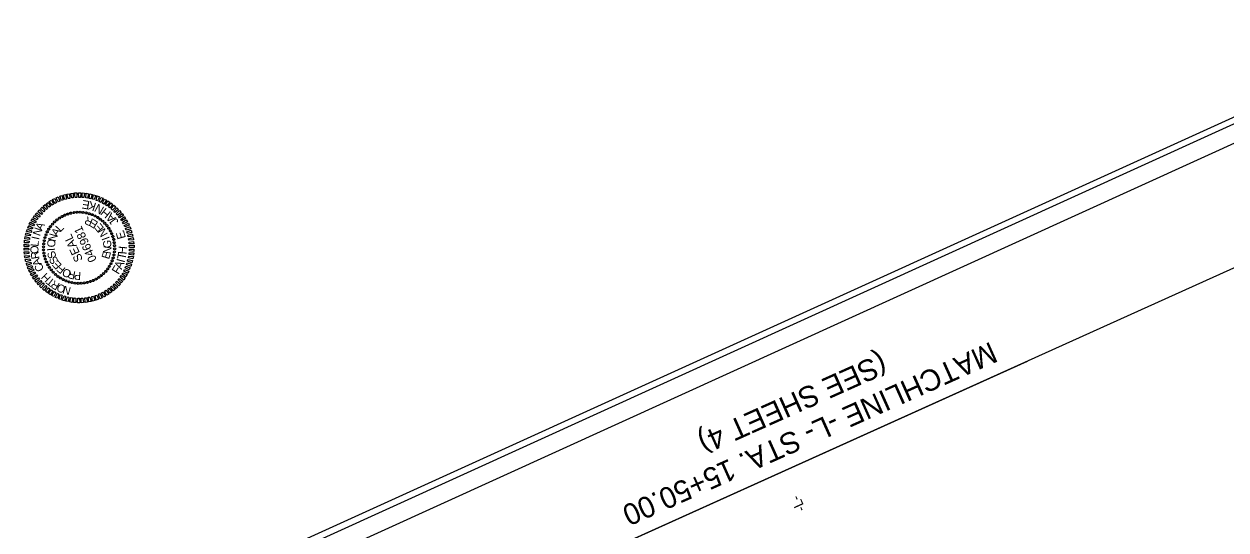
# Model space of a CAD drawing. Extents: x 2097307 to 2099001, y 683921 to 685907.
# Drawn here: x 2097307 to 2098154, y 685550 to 685907 of the extents above; entities that cross this region are included whole.
import ezdxf

# ---------------------------------------------------------------- set-up
doc = ezdxf.new("R2010")
doc.units = 0
for name, color, linetype in [('Matchline', 7, 'Continuous'), ('Matchline Text', 7, 'Continuous'), ('Prop Horizontal Alignment Station Label', 7, 'Continuous'), ('Sheet Layout Plan Border', 7, 'Continuous'), ('Sheet PE Seal Cell', 7, 'Continuous'), ('Sheet Plan CELL', 7, 'Continuous'), ('Sheet Plot Border Inside CELL', 7, 'Continuous'), ('Sheet Plot Border Outside CELL', 7, 'Continuous')]:
    doc.layers.add(name, color=color, linetype=linetype)

msp = doc.modelspace()

# ---------------------------------------------------------------- linework, layer by layer
at = {"layer": 'Matchline'}
msp.add_line((2097694.69, 685525.59), (2098013.7, 685669.59), dxfattribs=at)
at = {"layer": 'Sheet Layout Plan Border'}
msp.add_lwpolyline([(2098458.66, 685511.51), (2098911.14, 684517.12), (2097955.44, 684082.23), (2097420.98, 685256.77), (2097639.51, 685356.21), (2097584.97, 685476.06), (2098243.4, 685773.28), (2098379.01, 685475.27)], close=True, dxfattribs=at)
at = {"layer": 'Sheet PE Seal Cell'}
for p, q in [((2097339.58, 685773.8), (2097339.58, 685773.8)), ((2097341.68, 685774.26), (2097341.68, 685774.26)), ((2097343.88, 685774.49), (2097343.88, 685774.49)), ((2097346.07, 685774.5), (2097346.07, 685774.5)), ((2097348.26, 685774.4), (2097348.26, 685774.4)), ((2097350.42, 685774), (2097350.42, 685774)), ((2097352.57, 685773.5), (2097352.57, 685773.5)), ((2097326.61, 685766.08), (2097326.61, 685766.08)), ((2097328.1, 685767.64), (2097328.1, 685767.64)), ((2097329.76, 685769.05), (2097329.76, 685769.05)), ((2097331.6, 685770.33), (2097331.6, 685770.33)), ((2097333.43, 685771.49), (2097333.43, 685771.49)), ((2097335.41, 685772.45), (2097335.41, 685772.45)), ((2097337.48, 685773.22), (2097337.48, 685773.22)), ((2097354.6, 685772.78), (2097354.6, 685772.78)), ((2097356.65, 685771.9), (2097356.65, 685771.9)), ((2097358.51, 685770.82), (2097358.51, 685770.82)), ((2097360.35, 685769.57), (2097360.35, 685769.57)), ((2097362.06, 685768.21), (2097362.06, 685768.21)), ((2097363.62, 685766.72), (2097363.62, 685766.72)), ((2097365.04, 685765.05), (2097365.04, 685765.05)), ((2097321.32, 685756.59), (2097321.32, 685756.59)), ((2097322.04, 685758.62), (2097322.04, 685758.62)), ((2097322.92, 685760.67), (2097322.92, 685760.67)), ((2097324, 685762.53), (2097324, 685762.53)), ((2097325.25, 685764.36), (2097325.25, 685764.36)), ((2097366.31, 685763.22), (2097366.31, 685763.22)), ((2097367.48, 685761.39), (2097367.48, 685761.39)), ((2097368.43, 685759.4), (2097368.43, 685759.4)), ((2097369.21, 685757.34), (2097369.21, 685757.34)), ((2097320.32, 685750.09), (2097320.32, 685750.09)), ((2097320.42, 685752.28), (2097320.42, 685752.28)), ((2097320.81, 685754.44), (2097320.81, 685754.44)), ((2097345.4, 685749.42), (2097345.4, 685749.42)), ((2097369.78, 685755.24), (2097369.78, 685755.24)), ((2097370.24, 685753.14), (2097370.24, 685753.14)), ((2097370.47, 685750.94), (2097370.47, 685750.94)), ((2097370.48, 685748.74), (2097370.48, 685748.74)), ((2097320.33, 685747.9), (2097320.33, 685747.9)), ((2097320.56, 685745.7), (2097320.56, 685745.7)), ((2097321.02, 685743.6), (2097321.02, 685743.6)), ((2097321.59, 685741.5), (2097321.59, 685741.5)), ((2097368.76, 685740.22), (2097368.76, 685740.22)), ((2097369.48, 685742.25), (2097369.48, 685742.25)), ((2097369.99, 685744.4), (2097369.99, 685744.4)), ((2097370.38, 685746.56), (2097370.38, 685746.56)), ((2097322.37, 685739.43), (2097322.37, 685739.43)), ((2097323.32, 685737.45), (2097323.32, 685737.45)), ((2097324.49, 685735.62), (2097324.49, 685735.62)), ((2097325.76, 685733.78), (2097325.76, 685733.78)), ((2097327.18, 685732.12), (2097327.18, 685732.12)), ((2097362.7, 685731.2), (2097362.7, 685731.2)), ((2097364.19, 685732.75), (2097364.19, 685732.75)), ((2097365.55, 685734.47), (2097365.55, 685734.47)), ((2097366.8, 685736.3), (2097366.8, 685736.3)), ((2097367.88, 685738.17), (2097367.88, 685738.17)), ((2097328.74, 685730.63), (2097328.74, 685730.63)), ((2097330.45, 685729.27), (2097330.45, 685729.27)), ((2097332.29, 685728.01), (2097332.29, 685728.01)), ((2097334.15, 685726.94), (2097334.15, 685726.94)), ((2097336.2, 685726.06), (2097336.2, 685726.06)), ((2097338.23, 685725.34), (2097338.23, 685725.34)), ((2097340.38, 685724.83), (2097340.38, 685724.83)), ((2097342.54, 685724.44), (2097342.54, 685724.44)), ((2097344.73, 685724.34), (2097344.73, 685724.34)), ((2097346.92, 685724.35), (2097346.92, 685724.35)), ((2097349.12, 685724.58), (2097349.12, 685724.58)), ((2097351.22, 685725.04), (2097351.22, 685725.04)), ((2097353.32, 685725.61), (2097353.32, 685725.61)), ((2097355.39, 685726.39), (2097355.39, 685726.39)), ((2097357.37, 685727.34), (2097357.37, 685727.34)), ((2097359.2, 685728.51), (2097359.2, 685728.51)), ((2097361.04, 685729.78), (2097361.04, 685729.78))]:
    msp.add_line(p, q, dxfattribs=at)
for points in [[(2097326.38, 685779.38), (2097324.4, 685782.05), (2097325.88, 685782.89), (2097327.39, 685780.06)], [(2097328.44, 685780.65), (2097326.73, 685783.44), (2097328.24, 685784.24), (2097329.49, 685781.24)], [(2097330.7, 685781.73), (2097329.21, 685784.63), (2097330.76, 685785.33), (2097331.79, 685782.23)], [(2097332.99, 685782.72), (2097331.74, 685785.72), (2097333.28, 685786.31), (2097334.13, 685783.13)], [(2097335.28, 685783.49), (2097334.23, 685786.52), (2097335.86, 685787.04), (2097336.48, 685783.76)], [(2097337.77, 685784.18), (2097336.85, 685787.17), (2097338.54, 685787.55), (2097338.89, 685784.25)], [(2097340.22, 685784.58), (2097339.53, 685787.67), (2097341.18, 685788.04), (2097341.34, 685784.65)], [(2097342.72, 685784.89), (2097342.25, 685788.09), (2097343.93, 685788.14), (2097343.9, 685784.83)], [(2097345.13, 685784.89), (2097344.9, 685788.19), (2097346.62, 685788.15), (2097346.34, 685784.89)], [(2097347.64, 685784.94), (2097347.6, 685788.05), (2097349.32, 685788.01), (2097348.75, 685784.78)], [(2097350.09, 685784.73), (2097350.3, 685787.9), (2097351.99, 685787.57), (2097351.24, 685784.38)], [(2097352.54, 685784.2), (2097352.96, 685787.36), (2097354.68, 685787.09), (2097353.67, 685784)], [(2097354.89, 685783.62), (2097355.58, 685786.79), (2097357.22, 685786.33), (2097356, 685783.35)], [(2097357.34, 685782.81), (2097358.15, 685785.98), (2097359.71, 685785.32), (2097358.4, 685782.42)], [(2097359.62, 685782.04), (2097360.71, 685784.95), (2097362.3, 685784.35), (2097360.65, 685781.46)], [(2097361.86, 685780.86), (2097363.15, 685783.81), (2097364.66, 685783.01), (2097362.84, 685780.26)], [(2097364.01, 685779.75), (2097365.56, 685782.49), (2097366.97, 685781.7), (2097365.01, 685779)], [(2097317.29, 685771.12), (2097314.53, 685772.95), (2097315.67, 685774.18), (2097317.9, 685772.06)], [(2097318.83, 685772.92), (2097316.24, 685774.99), (2097317.43, 685776.24), (2097319.62, 685773.83)], [(2097320.59, 685774.72), (2097318.15, 685776.95), (2097319.33, 685778.1), (2097321.34, 685775.61)], [(2097322.45, 685776.44), (2097320.08, 685778.87), (2097321.45, 685779.83), (2097323.26, 685777.19)], [(2097324.38, 685777.98), (2097322.21, 685780.45), (2097323.64, 685781.43), (2097325.21, 685778.69)], [(2097366.06, 685778.26), (2097367.75, 685781.07), (2097369.12, 685779.99), (2097367, 685777.65)], [(2097368.04, 685776.8), (2097369.93, 685779.42), (2097371.2, 685778.3), (2097368.9, 685775.99)], [(2097369.91, 685775.24), (2097372.01, 685777.62), (2097373.18, 685776.5), (2097370.7, 685774.22)], [(2097371.65, 685773.34), (2097373.9, 685775.63), (2097374.96, 685774.4), (2097372.4, 685772.53)], [(2097373.24, 685771.42), (2097375.67, 685773.68), (2097376.69, 685772.28), (2097373.9, 685770.57)], [(2097312.43, 685762.48), (2097309.4, 685763.47), (2097309.99, 685765.06), (2097312.84, 685763.5)], [(2097313.34, 685764.82), (2097310.34, 685765.98), (2097311.13, 685767.5), (2097313.96, 685765.87)], [(2097314.49, 685767), (2097311.57, 685768.36), (2097312.49, 685769.82), (2097315.11, 685767.94)], [(2097315.82, 685769.03), (2097312.99, 685770.65), (2097313.97, 685772.14), (2097316.44, 685770.08)], [(2097374.73, 685769.47), (2097377.31, 685771.52), (2097378.13, 685770.08), (2097375.36, 685768.44)], [(2097376, 685767.41), (2097378.68, 685769.23), (2097379.57, 685767.77), (2097376.63, 685766.38)], [(2097377.26, 685765.23), (2097380.11, 685766.81), (2097380.75, 685765.28), (2097377.71, 685764.12)], [(2097310.44, 685755.26), (2097307.07, 685755.65), (2097307.49, 685757.27), (2097310.53, 685756.51)], [(2097310.96, 685757.75), (2097307.69, 685758.29), (2097308.15, 685759.93), (2097311.2, 685758.9)], [(2097311.58, 685760.12), (2097308.36, 685760.91), (2097308.96, 685762.5), (2097311.87, 685761.3)], [(2097378.21, 685763.03), (2097381.17, 685764.37), (2097381.8, 685762.85), (2097378.66, 685761.92)], [(2097379.11, 685760.69), (2097382.15, 685761.85), (2097382.56, 685760.23), (2097379.42, 685759.52)], [(2097379.74, 685758.34), (2097382.84, 685759.26), (2097383.29, 685757.65), (2097380.1, 685757.19)], [(2097380.29, 685755.79), (2097383.46, 685756.68), (2097383.8, 685754.97), (2097380.5, 685754.73)], [(2097309.99, 685747.92), (2097306.65, 685747.66), (2097306.61, 685749.18), (2097309.83, 685749.11)], [(2097309.92, 685750.36), (2097306.72, 685750.27), (2097306.72, 685751.98), (2097309.97, 685751.59)], [(2097310.02, 685752.93), (2097306.86, 685752.98), (2097307.02, 685754.69), (2097310.17, 685754.04)], [(2097380.7, 685753.34), (2097383.83, 685753.94), (2097384.01, 685752.32), (2097380.81, 685752.24)], [(2097380.81, 685750.92), (2097384.15, 685751.18), (2097384.19, 685749.65), (2097380.97, 685749.73)], [(2097380.88, 685748.48), (2097384.08, 685748.56), (2097384.08, 685746.86), (2097380.83, 685747.25)], [(2097310.1, 685745.5), (2097306.97, 685744.9), (2097306.78, 685746.51), (2097309.99, 685746.6)], [(2097310.51, 685743.04), (2097307.34, 685742.15), (2097307, 685743.86), (2097310.3, 685744.1)], [(2097311.06, 685740.49), (2097307.96, 685739.58), (2097307.51, 685741.18), (2097310.7, 685741.65)], [(2097379.84, 685741.09), (2097383.11, 685740.54), (2097382.65, 685738.9), (2097379.6, 685739.93)], [(2097380.36, 685743.57), (2097383.72, 685743.18), (2097383.31, 685741.56), (2097380.27, 685742.32)], [(2097380.78, 685745.91), (2097383.93, 685745.86), (2097383.78, 685744.14), (2097380.63, 685744.79)], [(2097311.69, 685738.14), (2097308.65, 685736.98), (2097308.24, 685738.61), (2097311.38, 685739.32)], [(2097312.59, 685735.81), (2097309.63, 685734.46), (2097308.99, 685735.98), (2097312.14, 685736.92)], [(2097313.54, 685733.6), (2097310.68, 685732.03), (2097310.05, 685733.55), (2097313.09, 685734.71)], [(2097314.8, 685731.43), (2097312.12, 685729.6), (2097311.23, 685731.07), (2097314.17, 685732.46)], [(2097376.31, 685731.84), (2097379.23, 685730.48), (2097378.31, 685729.01), (2097375.69, 685730.9)], [(2097377.46, 685734.01), (2097380.46, 685732.85), (2097379.67, 685731.34), (2097376.84, 685732.96)], [(2097378.37, 685736.35), (2097381.4, 685735.37), (2097380.81, 685733.78), (2097377.95, 685735.34)], [(2097379.22, 685738.71), (2097382.44, 685737.92), (2097381.84, 685736.34), (2097378.93, 685737.54)], [(2097316.07, 685729.37), (2097313.49, 685727.32), (2097312.67, 685728.76), (2097315.44, 685730.4)], [(2097317.56, 685727.41), (2097315.13, 685725.15), (2097314.11, 685726.55), (2097316.9, 685728.26)], [(2097319.15, 685725.5), (2097316.9, 685723.21), (2097315.84, 685724.43), (2097318.4, 685726.31)], [(2097320.89, 685723.6), (2097318.79, 685721.21), (2097317.62, 685722.33), (2097320.1, 685724.61)], [(2097322.76, 685722.03), (2097320.87, 685719.41), (2097319.59, 685720.54), (2097321.89, 685722.85)], [(2097370.2, 685724.12), (2097372.65, 685721.88), (2097371.47, 685720.74), (2097369.46, 685723.23)], [(2097371.97, 685725.91), (2097374.56, 685723.85), (2097373.37, 685722.59), (2097371.18, 685725)], [(2097373.51, 685727.71), (2097376.27, 685725.89), (2097375.12, 685724.66), (2097372.9, 685726.77)], [(2097374.98, 685729.81), (2097377.8, 685728.18), (2097376.83, 685726.7), (2097374.36, 685728.76)], [(2097324.74, 685720.57), (2097323.05, 685717.77), (2097321.68, 685718.85), (2097323.8, 685721.19)], [(2097326.79, 685719.09), (2097325.24, 685716.35), (2097323.83, 685717.14), (2097325.79, 685719.84)], [(2097328.94, 685717.98), (2097327.65, 685715.03), (2097326.13, 685715.82), (2097327.96, 685718.57)], [(2097331.18, 685716.8), (2097330.09, 685713.89), (2097328.5, 685714.48), (2097330.15, 685717.37)], [(2097333.46, 685716.02), (2097332.65, 685712.85), (2097331.08, 685713.51), (2097332.4, 685716.42)], [(2097335.91, 685715.22), (2097335.21, 685712.04), (2097333.58, 685712.51), (2097334.8, 685715.48)], [(2097338.26, 685714.64), (2097337.83, 685711.48), (2097336.12, 685711.74), (2097337.13, 685714.84)], [(2097340.7, 685714.1), (2097340.5, 685710.93), (2097338.81, 685711.26), (2097339.55, 685714.46)], [(2097350.58, 685714.25), (2097351.27, 685711.16), (2097349.62, 685710.8), (2097349.46, 685714.18)], [(2097353.03, 685714.66), (2097353.95, 685711.67), (2097352.26, 685711.28), (2097351.91, 685714.59)], [(2097355.52, 685715.35), (2097356.57, 685712.31), (2097354.94, 685711.79), (2097354.32, 685715.08)], [(2097357.81, 685716.12), (2097359.06, 685713.12), (2097357.52, 685712.52), (2097356.67, 685715.71)], [(2097360.1, 685717.11), (2097361.59, 685714.21), (2097360.04, 685713.51), (2097359.01, 685716.61)], [(2097362.36, 685718.19), (2097364.07, 685715.39), (2097362.56, 685714.6), (2097361.31, 685717.6)], [(2097364.42, 685719.45), (2097366.4, 685716.79), (2097364.92, 685715.94), (2097363.41, 685718.77)], [(2097366.42, 685720.86), (2097368.59, 685718.38), (2097367.16, 685717.41), (2097365.58, 685720.15)], [(2097368.35, 685722.4), (2097370.72, 685719.96), (2097369.35, 685719), (2097367.54, 685721.64)], [(2097343.16, 685713.9), (2097343.2, 685710.79), (2097341.48, 685710.83), (2097342.05, 685714.05)], [(2097345.67, 685713.94), (2097345.9, 685710.64), (2097344.18, 685710.68), (2097344.46, 685713.94)], [(2097348.08, 685713.94), (2097348.55, 685710.75), (2097346.87, 685710.7), (2097346.9, 685714.01)]]:
    msp.add_lwpolyline(points, close=True, dxfattribs=at)
for centre, major_axis in [((2097337.45, 685773.21), (-0.228, 0.683)), ((2097339.56, 685773.81), (-0.168, 0.7)), ((2097341.71, 685774.22), (-0.106, 0.712)), ((2097343.88, 685774.45), (-0.044, 0.719)), ((2097346.07, 685774.49), (0.019, 0.72)), ((2097348.25, 685774.33), (0.082, 0.715)), ((2097350.41, 685773.99), (0.144, 0.705)), ((2097352.54, 685773.46), (0.205, 0.69)), ((2097354.6, 685772.75), (0.264, 0.67)), ((2097325.25, 685764.35), (-0.579, 0.429)), ((2097326.63, 685766.05), (-0.539, 0.477)), ((2097328.15, 685767.62), (-0.495, 0.523)), ((2097329.8, 685769.05), (-0.448, 0.564)), ((2097331.57, 685770.34), (-0.397, 0.601)), ((2097333.44, 685771.46), (-0.343, 0.633)), ((2097335.41, 685772.42), (-0.287, 0.66)), ((2097356.6, 685771.86), (0.322, 0.644)), ((2097358.52, 685770.79), (0.377, 0.614)), ((2097360.33, 685769.57), (0.429, 0.579)), ((2097362.03, 685768.19), (0.477, 0.539)), ((2097363.6, 685766.67), (0.523, 0.495)), ((2097365.04, 685765.02), (0.564, 0.448)), ((2097321.36, 685756.55), (-0.69, 0.205)), ((2097322.07, 685758.62), (-0.67, 0.264)), ((2097322.96, 685760.62), (-0.644, 0.322)), ((2097324.02, 685762.53), (-0.614, 0.377)), ((2097366.32, 685763.25), (0.601, 0.397)), ((2097367.45, 685761.37), (0.633, 0.343)), ((2097368.4, 685759.4), (0.66, 0.287)), ((2097369.19, 685757.36), (0.683, 0.228)), ((2097320.33, 685750.09), (-0.72, 0.019)), ((2097320.37, 685747.9), (-0.719, -0.044)), ((2097320.48, 685752.27), (-0.715, 0.082)), ((2097320.83, 685754.43), (-0.705, 0.144)), ((2097369.79, 685755.26), (0.7, 0.168)), ((2097370.21, 685753.11), (0.712, 0.106)), ((2097370.43, 685750.93), (0.719, 0.044)), ((2097370.47, 685748.75), (0.72, -0.019)), ((2097320.59, 685745.72), (-0.712, -0.106)), ((2097321.01, 685743.58), (-0.7, -0.168)), ((2097321.61, 685741.47), (-0.683, -0.228)), ((2097322.39, 685739.43), (-0.66, -0.287)), ((2097368.73, 685740.21), (0.67, -0.264)), ((2097369.44, 685742.28), (0.69, -0.205)), ((2097369.97, 685744.4), (0.705, -0.144)), ((2097370.32, 685746.56), (0.715, -0.082)), ((2097323.35, 685737.46), (-0.633, -0.343)), ((2097324.48, 685735.59), (-0.601, -0.397)), ((2097325.76, 685733.82), (-0.564, -0.448)), ((2097327.2, 685732.16), (-0.523, -0.495)), ((2097328.77, 685730.64), (-0.477, -0.539)), ((2097362.65, 685731.22), (0.495, -0.523)), ((2097364.17, 685732.79), (0.539, -0.477)), ((2097365.55, 685734.49), (0.579, -0.429)), ((2097366.78, 685736.3), (0.614, -0.377)), ((2097367.84, 685738.21), (0.644, -0.322)), ((2097330.47, 685729.27), (-0.429, -0.579)), ((2097332.28, 685728.04), (-0.377, -0.614)), ((2097334.2, 685726.98), (-0.322, -0.644)), ((2097336.19, 685726.09), (-0.264, -0.67)), ((2097338.26, 685725.37), (-0.205, -0.69)), ((2097340.39, 685724.84), (-0.144, -0.705)), ((2097342.55, 685724.5), (-0.082, -0.715)), ((2097344.73, 685724.35), (-0.019, -0.72)), ((2097346.92, 685724.38), (0.044, -0.719)), ((2097349.09, 685724.61), (0.106, -0.712)), ((2097351.24, 685725.03), (0.168, -0.7)), ((2097353.34, 685725.63), (0.228, -0.683)), ((2097355.39, 685726.41), (0.287, -0.66)), ((2097357.35, 685727.37), (0.343, -0.633)), ((2097359.23, 685728.5), (0.397, -0.601)), ((2097361, 685729.78), (0.448, -0.564))]:
    msp.add_ellipse(centre, major_axis=major_axis, ratio=0.999708, dxfattribs=at)
at = {"layer": 'Sheet Plan CELL'}
msp.add_line((2098289.88, 685882.41), (2097334.17, 685447.53), dxfattribs=at)
at = {"layer": 'Sheet Plot Border Inside CELL'}
msp.add_lwpolyline([(2098977, 684378.44), (2098287, 685894.78), (2097326.75, 685457.84), (2098016.75, 683941.49)], close=True, dxfattribs=at)
at = {"layer": 'Sheet Plot Border Outside CELL'}
msp.add_lwpolyline([(2099000.59, 684374.9), (2098303.35, 685907.17), (2097306.68, 685453.65), (2098003.93, 683921.37)], close=True, dxfattribs=at)

# ---------------------------------------------------------------- texts
at = {"layer": 'Matchline Text'}
for s, p in [('MATCHLINE -L- STA. 15+50.00', (2097987.84, 685683.47)), ('(SEE SHEET 4)', (2097910.46, 685675.53))]:
    msp.add_text(s, height=15, rotation=204.12202, dxfattribs=at).set_placement(p)
at = {"layer": 'Prop Horizontal Alignment Station Label'}
msp.add_text('-L-', height=7, rotation=114.46742, dxfattribs=at).set_placement((2097857.53, 685565.18))
at = {"layer": 'Sheet PE Seal Cell'}
for s, height, rotation, p in [('E', 6, 169.96044, (2097353.31, 685782.24)), ('K', 6, 161.67652, (2097357.95, 685780.76)), ('N', 6, 150.95069, (2097363.57, 685777.88)), ('H', 6, 140.9667, (2097368.23, 685774.3)), ('A', 6, 132.12639, (2097371.78, 685770.49)), ('A', 5.64, 63.08457, (2097319.21, 685761.23)), ('L', 5.64, 46.86827, (2097332.3, 685760.21)), ('R', 5.64, 156.94882, (2097355.72, 685769.6)), ('E', 5.64, 147.5915, (2097359.32, 685767.34)), ('E', 5.64, 128.87918, (2097363.29, 685763.33)), ('J', 6, 126.86858, (2097373.6, 685767.99)), ('I', 5.64, 77.48756, (2097317.22, 685754.72)), ('N', 5.64, 70.28632, (2097317.74, 685757.32)), ('N', 5.64, 74.94403, (2097328.78, 685753.34)), ('A', 5.64, 56.22768, (2097329.97, 685757.01)), ('SEAL', 5.998, 114.46742, (2097348.27, 685741.06)), ('046981', 5.998, 114.46742, (2097358.06, 685740.93)), ('N', 5.64, 119.5238, (2097365.89, 685759.07)), ('I', 5.64, 110.16862, (2097367.14, 685755.96)), ('E', 6, 105.5251, (2097378.42, 685756.45)), ('.', 6, 112.63444, (2097377.3, 685760.48)), ('O', 5.64, 91.88858, (2097316.85, 685745.27)), ('L', 5.64, 84.68829, (2097316.71, 685750.04)), ('O', 5.64, 84.3009, (2097328.35, 685749.46)), ('I', 5.64, 93.65702, (2097328.54, 685747.35)), ('N', 5.64, 82.10137, (2097367.65, 685744.82)), ('G', 5.64, 91.45765, (2097368.13, 685749.21)), ('H', 6, 85.34076, (2097378.82, 685744.62)), ('R', 5.64, 99.08851, (2097317.56, 685741.91)), ('A', 5.64, 113.48774, (2097319.12, 685738.01)), ('S', 5.64, 112.36782, (2097329.69, 685743.15)), ('S', 5.64, 121.72302, (2097331.22, 685739.89)), ('E', 5.64, 131.07848, (2097333.61, 685737.18)), ('E', 5.64, 72.7443, (2097366.44, 685740.97)), ('I', 6, 74.73858, (2097377.37, 685738.56)), ('T', 6, 78.54053, (2097378.02, 685740.7)), ('C', 5.64, 120.68729, (2097321.02, 685734.54)), ('H', 5.64, 135.08689, (2097325.99, 685728.45)), ('F', 5.64, 140.43445, (2097336.3, 685734.89)), ('O', 5.64, 159.14865, (2097340.35, 685733.11)), ('R', 5.64, 168.50707, (2097343.3, 685732.53)), ('P', 5.64, 177.8663, (2097346.88, 685732.4)), ('F', 6, 58.88166, (2097373.18, 685730.23)), ('A', 6, 65.89827, (2097375.32, 685733.77)), ('T', 5.64, 142.28719, (2097328.84, 685726.17)), ('R', 5.64, 149.48792, (2097332.25, 685723.99)), ('O', 5.64, 156.68916, (2097336.5, 685722.13)), ('N', 5.64, 163.89092, (2097340.09, 685721.24))]:
    msp.add_text(s, height=height, rotation=rotation, dxfattribs=at).set_placement(p)

doc.saveas('drawing.dxf')
